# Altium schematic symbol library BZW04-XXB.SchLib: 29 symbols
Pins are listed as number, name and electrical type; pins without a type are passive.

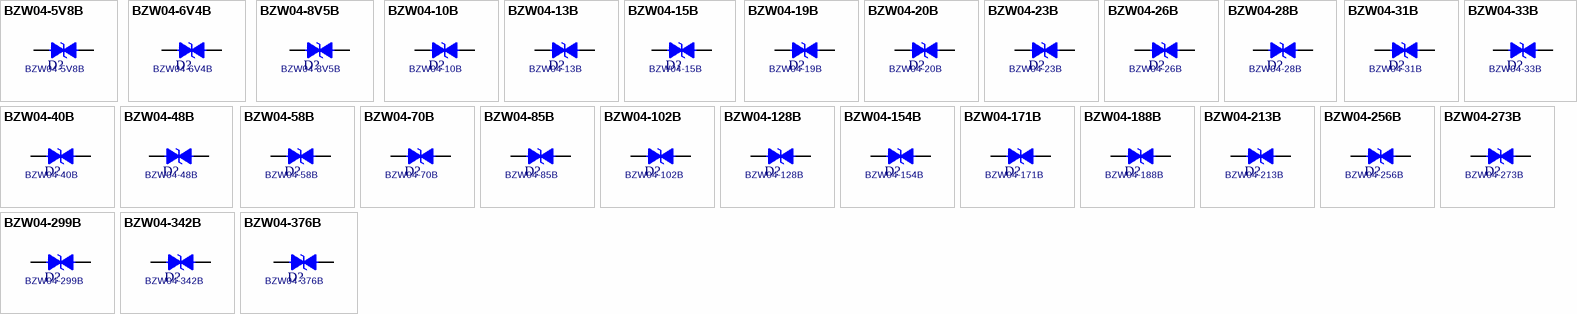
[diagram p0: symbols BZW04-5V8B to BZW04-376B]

## BZW04-5V8B
designator D?
footprint ST_DO15B
pins: 1, 2

## BZW04-6V4B
designator D?
footprint ST_DO15B
pins: 1, 2

## BZW04-8V5B
designator D?
footprint ST_DO15B
pins: 1, 2

## BZW04-10B
designator D?
footprint ST_DO15B
pins: 1, 2

## BZW04-13B
designator D?
footprint ST_DO15B
pins: 1, 2

## BZW04-15B
designator D?
footprint ST_DO15B
pins: 1, 2

## BZW04-19B
designator D?
footprint ST_DO15B
pins: 1, 2

## BZW04-20B
designator D?
footprint ST_DO15B
pins: 1, 2

## BZW04-23B
designator D?
footprint ST_DO15B
pins: 1, 2

## BZW04-26B
designator D?
footprint ST_DO15B
pins: 1, 2

## BZW04-28B
designator D?
footprint ST_DO15B
pins: 1, 2

## BZW04-31B
designator D?
footprint ST_DO15B
pins: 1, 2

## BZW04-33B
designator D?
footprint ST_DO15B
pins: 1, 2

## BZW04-40B
designator D?
footprint ST_DO15B
pins: 1, 2

## BZW04-48B
designator D?
footprint ST_DO15B
pins: 1, 2

## BZW04-58B
designator D?
footprint ST_DO15B
pins: 1, 2

## BZW04-70B
designator D?
footprint ST_DO15B
pins: 1, 2

## BZW04-85B
designator D?
footprint ST_DO15B
pins: 1, 2

## BZW04-102B
designator D?
footprint ST_DO15B
pins: 1, 2

## BZW04-128B
designator D?
footprint ST_DO15B
pins: 1, 2

## BZW04-154B
designator D?
footprint ST_DO15B
pins: 1, 2

## BZW04-171B
designator D?
footprint ST_DO15B
pins: 1, 2

## BZW04-188B
designator D?
footprint ST_DO15B
pins: 1, 2

## BZW04-213B
designator D?
footprint ST_DO15B
pins: 1, 2

## BZW04-256B
designator D?
footprint ST_DO15B
pins: 1, 2

## BZW04-273B
designator D?
footprint ST_DO15B
pins: 1, 2

## BZW04-299B
designator D?
footprint ST_DO15B
pins: 1, 2

## BZW04-342B
designator D?
footprint ST_DO15B
pins: 1, 2

## BZW04-376B
designator D?
footprint ST_DO15B
pins: 1, 2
